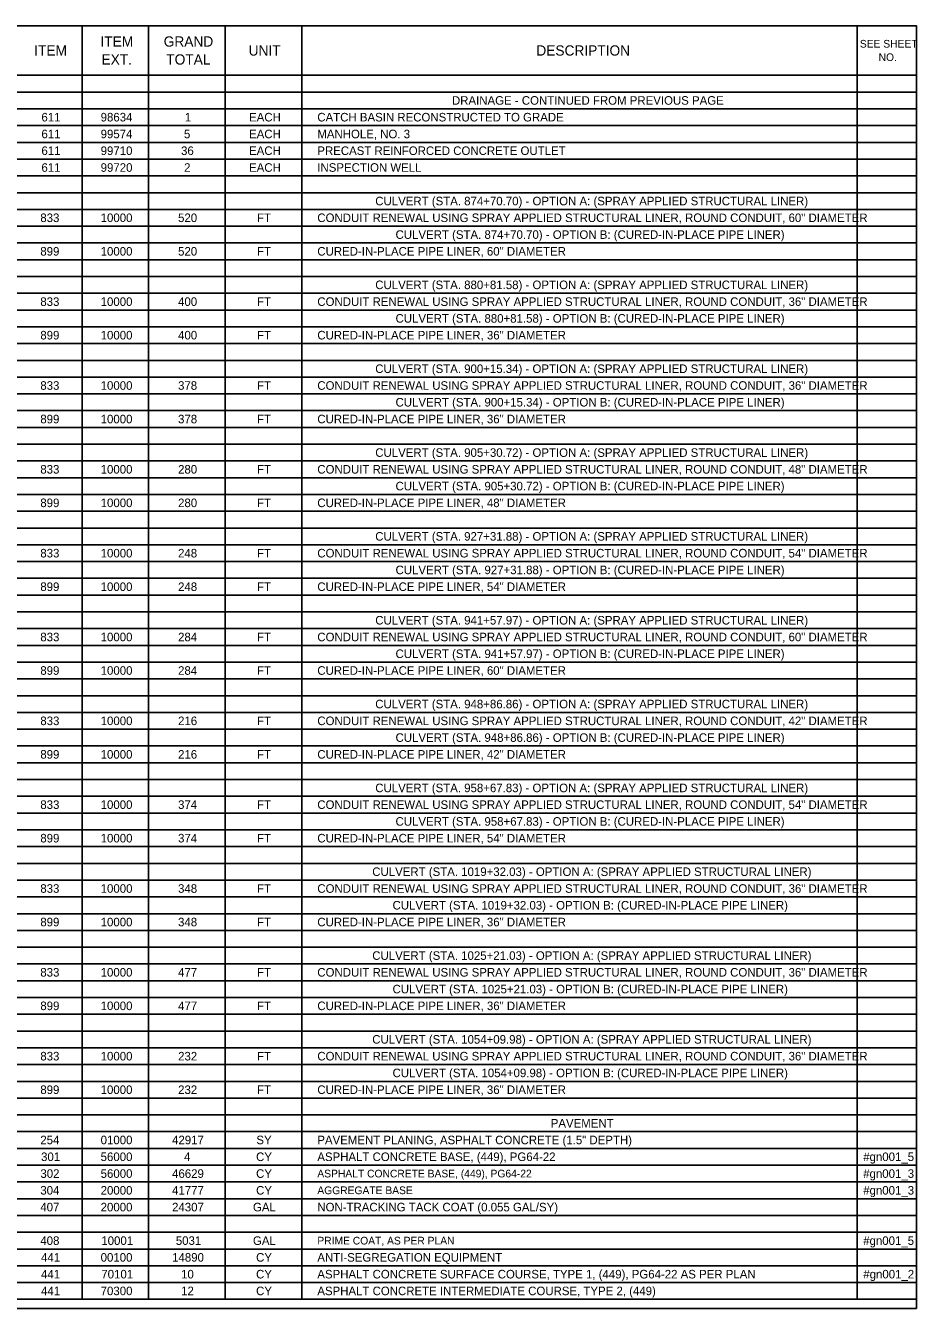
# Model space of a CAD drawing. Extents: x -542 to 295, y -281 to 32.
# Drawn here: x -400.45 to -385.84, y -70.59 to -49.59 of the extents above; entities that cross this region are included whole.
import ezdxf

# ---------------------------------------------------------------- set-up
doc = ezdxf.new("R2010")
doc.units = 0
for name, color, linetype in [('SC_Scratch1', 7, 'Continuous'), ('SH_Data', 7, 'Continuous'), ('SH_Text', 7, 'Continuous')]:
    doc.layers.add(name, color=color, linetype=linetype)

msp = doc.modelspace()

# ---------------------------------------------------------------- linework, layer by layer
at = {"layer": 'SC_Scratch1'}
msp.add_lwpolyline([(-416.359, -49.593), (-385.859, -49.593), (-385.859, -70.593), (-416.359, -70.593)], close=True, dxfattribs=at)
at = {"layer": 'SH_Data'}
for p, q in [((-416.359, -49.593), (-385.859, -49.593)), ((-399.523, -49.593), (-399.523, -70.444)), ((-398.437, -49.593), (-398.437, -70.444)), ((-397.182, -49.593), (-397.182, -70.444)), ((-395.926, -49.593), (-395.926, -70.444)), ((-386.827, -49.593), (-386.827, -70.444)), ((-385.859, -49.593), (-385.859, -70.444)), ((-416.359, -50.405), (-385.859, -50.405)), ((-416.359, -50.68), (-385.859, -50.68)), ((-416.359, -50.954), (-385.859, -50.954)), ((-416.359, -51.229), (-385.859, -51.229)), ((-416.359, -51.503), (-385.859, -51.503)), ((-416.359, -51.778), (-385.859, -51.778)), ((-416.359, -52.052), (-385.859, -52.052)), ((-416.359, -52.327), (-385.859, -52.327)), ((-416.359, -52.327), (-385.859, -52.327)), ((-416.359, -52.601), (-385.859, -52.601)), ((-416.359, -52.876), (-385.859, -52.876)), ((-416.359, -53.15), (-385.859, -53.15)), ((-416.359, -53.425), (-385.859, -53.425)), ((-416.359, -53.699), (-385.859, -53.699)), ((-416.359, -53.974), (-385.859, -53.974)), ((-416.359, -54.248), (-385.859, -54.248)), ((-416.359, -54.523), (-385.859, -54.523)), ((-416.359, -54.797), (-385.859, -54.797)), ((-416.359, -55.072), (-385.859, -55.072)), ((-416.359, -55.346), (-385.859, -55.346)), ((-416.359, -55.621), (-385.859, -55.621)), ((-416.359, -55.895), (-385.859, -55.895)), ((-416.359, -56.17), (-385.859, -56.17)), ((-416.359, -56.444), (-385.859, -56.444)), ((-416.359, -56.719), (-385.859, -56.719)), ((-416.359, -56.993), (-385.859, -56.993)), ((-416.359, -57.268), (-385.859, -57.268)), ((-416.359, -57.542), (-385.859, -57.542)), ((-416.359, -57.817), (-385.859, -57.817)), ((-416.359, -58.091), (-385.859, -58.091)), ((-416.359, -58.366), (-385.859, -58.366)), ((-416.359, -58.64), (-385.859, -58.64)), ((-416.359, -58.915), (-385.859, -58.915)), ((-416.359, -59.189), (-385.859, -59.189)), ((-416.359, -59.464), (-385.859, -59.464)), ((-416.359, -59.738), (-385.859, -59.738)), ((-416.359, -60.013), (-385.859, -60.013)), ((-416.359, -60.287), (-385.859, -60.287)), ((-416.359, -60.562), (-385.859, -60.562)), ((-416.359, -60.836), (-385.859, -60.836)), ((-416.359, -61.111), (-385.859, -61.111)), ((-416.359, -61.385), (-385.859, -61.385)), ((-416.359, -61.66), (-385.859, -61.66)), ((-416.359, -61.935), (-385.859, -61.935)), ((-416.359, -62.209), (-385.859, -62.209)), ((-416.359, -62.484), (-385.859, -62.484)), ((-416.359, -62.758), (-385.859, -62.758)), ((-416.359, -63.033), (-385.859, -63.033)), ((-416.359, -63.307), (-385.859, -63.307)), ((-416.359, -63.582), (-385.859, -63.582)), ((-416.359, -63.856), (-385.859, -63.856)), ((-416.359, -64.131), (-385.859, -64.131)), ((-416.359, -64.405), (-385.859, -64.405)), ((-416.359, -64.68), (-385.859, -64.68)), ((-416.359, -64.954), (-385.859, -64.954)), ((-416.359, -65.229), (-385.859, -65.229)), ((-416.359, -65.503), (-385.859, -65.503)), ((-416.359, -65.778), (-385.859, -65.778)), ((-416.359, -66.052), (-385.859, -66.052)), ((-416.359, -66.327), (-385.859, -66.327)), ((-416.359, -66.601), (-385.859, -66.601)), ((-416.359, -66.876), (-385.859, -66.876)), ((-416.359, -67.15), (-385.859, -67.15)), ((-416.359, -67.425), (-385.859, -67.425)), ((-416.359, -67.425), (-385.859, -67.425)), ((-416.359, -67.699), (-385.859, -67.699)), ((-416.359, -67.974), (-385.859, -67.974)), ((-416.359, -68.248), (-385.859, -68.248)), ((-416.359, -68.523), (-385.859, -68.523)), ((-416.359, -68.797), (-385.859, -68.797)), ((-416.359, -69.072), (-385.859, -69.072)), ((-416.359, -69.346), (-385.859, -69.346)), ((-416.359, -69.621), (-385.859, -69.621)), ((-416.359, -69.895), (-385.859, -69.895)), ((-416.359, -70.17), (-385.859, -70.17)), ((-416.359, -70.444), (-385.859, -70.444)), ((-416.359, -70.444), (-385.859, -70.444))]:
    msp.add_line(p, q, dxfattribs=at)

# ---------------------------------------------------------------- texts
at = {"layer": 'SH_Text'}
for s, height, p in [('ITEM', 0.168, (-399.222, -49.936)), ('GRAND ', 0.168, (-398.186, -49.936)), ('ITEM', 0.168, (-400.307, -50.083)), ('UNIT', 0.168, (-396.795, -50.083)), ('DESCRIPTION', 0.168, (-392.083, -50.083)), ('SEE SHEET ', 0.126, (-386.784, -49.952)), ('EXT.', 0.168, (-399.205, -50.23)), ('TOTAL', 0.168, (-398.144, -50.23)), ('NO.', 0.126, (-386.477, -50.172)), ('DRAINAGE - CONTINUED FROM PREVIOUS PAGE', 0.14, (-393.465, -50.887)), ('611', 0.14, (-400.189, -51.161)), ('98634', 0.14, (-399.219, -51.161)), ('1', 0.14, (-397.841, -51.161)), ('EACH', 0.14, (-396.788, -51.161)), ('CATCH BASIN RECONSTRUCTED TO GRADE', 0.14, (-395.67, -51.161)), ('611', 0.14, (-400.189, -51.436)), ('99574', 0.14, (-399.219, -51.436)), ('5', 0.14, (-397.854, -51.436)), ('EACH', 0.14, (-396.788, -51.436)), ('MANHOLE, NO. 3', 0.14, (-395.67, -51.436)), ('611', 0.14, (-400.189, -51.71)), ('99710', 0.14, (-399.219, -51.71)), ('36', 0.14, (-397.902, -51.71)), ('EACH', 0.14, (-396.788, -51.71)), ('PRECAST REINFORCED CONCRETE OUTLET', 0.14, (-395.67, -51.71)), ('611', 0.14, (-400.189, -51.985)), ('99720', 0.14, (-399.219, -51.985)), ('2', 0.14, (-397.852, -51.985)), ('EACH', 0.14, (-396.788, -51.985)), ('INSPECTION WELL', 0.14, (-395.67, -51.985)), ('CULVERT (STA. 874+70.70) - OPTION A: (SPRAY APPLIED STRUCTURAL LINER)', 0.14, (-394.721, -52.534)), ('833', 0.14, (-400.207, -52.808)), ('10000', 0.14, (-399.219, -52.808)), ('520', 0.14, (-397.951, -52.808)), ('FT', 0.14, (-396.658, -52.808)), ('CONDUIT RENEWAL USING SPRAY APPLIED STRUCTURAL LINER, ROUND CONDUIT, 60" DIAMETER', 0.14, (-395.67, -52.808)), ('CULVERT (STA. 874+70.70) - OPTION B: (CURED-IN-PLACE PIPE LINER)', 0.14, (-394.389, -53.083)), ('899', 0.14, (-400.207, -53.357)), ('10000', 0.14, (-399.219, -53.357)), ('520', 0.14, (-397.951, -53.357)), ('FT', 0.14, (-396.658, -53.357)), ('CURED-IN-PLACE PIPE LINER, 60" DIAMETER', 0.14, (-395.67, -53.357)), ('CULVERT (STA. 880+81.58) - OPTION A: (SPRAY APPLIED STRUCTURAL LINER)', 0.14, (-394.721, -53.906)), ('833', 0.14, (-400.207, -54.181)), ('10000', 0.14, (-399.219, -54.181)), ('400', 0.14, (-397.951, -54.181)), ('FT', 0.14, (-396.658, -54.181)), ('CONDUIT RENEWAL USING SPRAY APPLIED STRUCTURAL LINER, ROUND CONDUIT, 36" DIAMETER', 0.14, (-395.67, -54.181)), ('CULVERT (STA. 880+81.58) - OPTION B: (CURED-IN-PLACE PIPE LINER)', 0.14, (-394.389, -54.455)), ('899', 0.14, (-400.207, -54.73)), ('10000', 0.14, (-399.219, -54.73)), ('400', 0.14, (-397.951, -54.73)), ('FT', 0.14, (-396.658, -54.73)), ('CURED-IN-PLACE PIPE LINER, 36" DIAMETER', 0.14, (-395.67, -54.73)), ('CULVERT (STA. 900+15.34) - OPTION A: (SPRAY APPLIED STRUCTURAL LINER)', 0.14, (-394.721, -55.279)), ('833', 0.14, (-400.207, -55.554)), ('10000', 0.14, (-399.219, -55.554)), ('378', 0.14, (-397.951, -55.554)), ('FT', 0.14, (-396.658, -55.554)), ('CONDUIT RENEWAL USING SPRAY APPLIED STRUCTURAL LINER, ROUND CONDUIT, 36" DIAMETER', 0.14, (-395.67, -55.554)), ('CULVERT (STA. 900+15.34) - OPTION B: (CURED-IN-PLACE PIPE LINER)', 0.14, (-394.389, -55.828)), ('899', 0.14, (-400.207, -56.103)), ('10000', 0.14, (-399.219, -56.103)), ('378', 0.14, (-397.951, -56.103)), ('FT', 0.14, (-396.658, -56.103)), ('CURED-IN-PLACE PIPE LINER, 36" DIAMETER', 0.14, (-395.67, -56.103)), ('CULVERT (STA. 905+30.72) - OPTION A: (SPRAY APPLIED STRUCTURAL LINER)', 0.14, (-394.721, -56.652)), ('833', 0.14, (-400.207, -56.926)), ('10000', 0.14, (-399.219, -56.926)), ('280', 0.14, (-397.951, -56.926)), ('FT', 0.14, (-396.658, -56.926)), ('CONDUIT RENEWAL USING SPRAY APPLIED STRUCTURAL LINER, ROUND CONDUIT, 48" DIAMETER', 0.14, (-395.67, -56.926)), ('CULVERT (STA. 905+30.72) - OPTION B: (CURED-IN-PLACE PIPE LINER)', 0.14, (-394.389, -57.201)), ('899', 0.14, (-400.207, -57.475)), ('10000', 0.14, (-399.219, -57.475)), ('280', 0.14, (-397.951, -57.475)), ('FT', 0.14, (-396.658, -57.475)), ('CURED-IN-PLACE PIPE LINER, 48" DIAMETER', 0.14, (-395.67, -57.475)), ('CULVERT (STA. 927+31.88) - OPTION A: (SPRAY APPLIED STRUCTURAL LINER)', 0.14, (-394.721, -58.024)), ('833', 0.14, (-400.207, -58.299)), ('10000', 0.14, (-399.219, -58.299)), ('248', 0.14, (-397.951, -58.299)), ('FT', 0.14, (-396.658, -58.299)), ('CONDUIT RENEWAL USING SPRAY APPLIED STRUCTURAL LINER, ROUND CONDUIT, 54" DIAMETER', 0.14, (-395.67, -58.299)), ('CULVERT (STA. 927+31.88) - OPTION B: (CURED-IN-PLACE PIPE LINER)', 0.14, (-394.389, -58.573)), ('899', 0.14, (-400.207, -58.848)), ('10000', 0.14, (-399.219, -58.848)), ('248', 0.14, (-397.951, -58.848)), ('FT', 0.14, (-396.658, -58.848)), ('CURED-IN-PLACE PIPE LINER, 54" DIAMETER', 0.14, (-395.67, -58.848)), ('CULVERT (STA. 941+57.97) - OPTION A: (SPRAY APPLIED STRUCTURAL LINER)', 0.14, (-394.721, -59.397)), ('833', 0.14, (-400.207, -59.671)), ('10000', 0.14, (-399.219, -59.671)), ('284', 0.14, (-397.951, -59.671)), ('FT', 0.14, (-396.658, -59.671)), ('CONDUIT RENEWAL USING SPRAY APPLIED STRUCTURAL LINER, ROUND CONDUIT, 60" DIAMETER', 0.14, (-395.67, -59.671)), ('CULVERT (STA. 941+57.97) - OPTION B: (CURED-IN-PLACE PIPE LINER)', 0.14, (-394.389, -59.946)), ('899', 0.14, (-400.207, -60.22)), ('10000', 0.14, (-399.219, -60.22)), ('284', 0.14, (-397.951, -60.22)), ('FT', 0.14, (-396.658, -60.22)), ('CURED-IN-PLACE PIPE LINER, 60" DIAMETER', 0.14, (-395.67, -60.22)), ('CULVERT (STA. 948+86.86) - OPTION A: (SPRAY APPLIED STRUCTURAL LINER)', 0.14, (-394.721, -60.769)), ('833', 0.14, (-400.207, -61.044)), ('10000', 0.14, (-399.219, -61.044)), ('216', 0.14, (-397.951, -61.044)), ('FT', 0.14, (-396.658, -61.044)), ('CONDUIT RENEWAL USING SPRAY APPLIED STRUCTURAL LINER, ROUND CONDUIT, 42" DIAMETER', 0.14, (-395.67, -61.044)), ('CULVERT (STA. 948+86.86) - OPTION B: (CURED-IN-PLACE PIPE LINER)', 0.14, (-394.389, -61.318)), ('899', 0.14, (-400.207, -61.593)), ('10000', 0.14, (-399.219, -61.593)), ('216', 0.14, (-397.951, -61.593)), ('FT', 0.14, (-396.658, -61.593)), ('CURED-IN-PLACE PIPE LINER, 42" DIAMETER', 0.14, (-395.67, -61.593)), ('CULVERT (STA. 958+67.83) - OPTION A: (SPRAY APPLIED STRUCTURAL LINER)', 0.14, (-394.721, -62.142)), ('833', 0.14, (-400.207, -62.416)), ('10000', 0.14, (-399.219, -62.416)), ('374', 0.14, (-397.951, -62.416)), ('FT', 0.14, (-396.658, -62.416)), ('CONDUIT RENEWAL USING SPRAY APPLIED STRUCTURAL LINER, ROUND CONDUIT, 54" DIAMETER', 0.14, (-395.67, -62.416)), ('CULVERT (STA. 958+67.83) - OPTION B: (CURED-IN-PLACE PIPE LINER)', 0.14, (-394.389, -62.691)), ('899', 0.14, (-400.207, -62.965)), ('10000', 0.14, (-399.219, -62.965)), ('374', 0.14, (-397.951, -62.965)), ('FT', 0.14, (-396.658, -62.965)), ('CURED-IN-PLACE PIPE LINER, 54" DIAMETER', 0.14, (-395.67, -62.965)), ('CULVERT (STA. 1019+32.03) - OPTION A: (SPRAY APPLIED STRUCTURAL LINER)', 0.14, (-394.77, -63.514)), ('833', 0.14, (-400.207, -63.789)), ('10000', 0.14, (-399.219, -63.789)), ('348', 0.14, (-397.951, -63.789)), ('FT', 0.14, (-396.658, -63.789)), ('CONDUIT RENEWAL USING SPRAY APPLIED STRUCTURAL LINER, ROUND CONDUIT, 36" DIAMETER', 0.14, (-395.67, -63.789)), ('CULVERT (STA. 1019+32.03) - OPTION B: (CURED-IN-PLACE PIPE LINER)', 0.14, (-394.438, -64.063)), ('899', 0.14, (-400.207, -64.338)), ('10000', 0.14, (-399.219, -64.338)), ('348', 0.14, (-397.951, -64.338)), ('FT', 0.14, (-396.658, -64.338)), ('CURED-IN-PLACE PIPE LINER, 36" DIAMETER', 0.14, (-395.67, -64.338)), ('CULVERT (STA. 1025+21.03) - OPTION A: (SPRAY APPLIED STRUCTURAL LINER)', 0.14, (-394.77, -64.887)), ('833', 0.14, (-400.207, -65.161)), ('10000', 0.14, (-399.219, -65.161)), ('477', 0.14, (-397.951, -65.161)), ('FT', 0.14, (-396.658, -65.161)), ('CONDUIT RENEWAL USING SPRAY APPLIED STRUCTURAL LINER, ROUND CONDUIT, 36" DIAMETER', 0.14, (-395.67, -65.161)), ('CULVERT (STA. 1025+21.03) - OPTION B: (CURED-IN-PLACE PIPE LINER)', 0.14, (-394.438, -65.436)), ('899', 0.14, (-400.207, -65.71)), ('10000', 0.14, (-399.219, -65.71)), ('477', 0.14, (-397.951, -65.71)), ('FT', 0.14, (-396.658, -65.71)), ('CURED-IN-PLACE PIPE LINER, 36" DIAMETER', 0.14, (-395.67, -65.71)), ('CULVERT (STA. 1054+09.98) - OPTION A: (SPRAY APPLIED STRUCTURAL LINER)', 0.14, (-394.77, -66.259)), ('833', 0.14, (-400.207, -66.534)), ('10000', 0.14, (-399.219, -66.534)), ('232', 0.14, (-397.95, -66.534)), ('FT', 0.14, (-396.658, -66.534)), ('CONDUIT RENEWAL USING SPRAY APPLIED STRUCTURAL LINER, ROUND CONDUIT, 36" DIAMETER', 0.14, (-395.67, -66.534)), ('CULVERT (STA. 1054+09.98) - OPTION B: (CURED-IN-PLACE PIPE LINER)', 0.14, (-394.438, -66.808)), ('899', 0.14, (-400.207, -67.083)), ('10000', 0.14, (-399.219, -67.083)), ('232', 0.14, (-397.95, -67.083)), ('FT', 0.14, (-396.658, -67.083)), ('CURED-IN-PLACE PIPE LINER, 36" DIAMETER', 0.14, (-395.67, -67.083)), ('PAVEMENT', 0.14, (-391.847, -67.632)), ('254', 0.14, (-400.207, -67.906)), ('01000', 0.14, (-399.219, -67.906)), ('42917', 0.14, (-398.049, -67.906)), ('SY', 0.14, (-396.668, -67.906)), ('PAVEMENT PLANING, ASPHALT CONCRETE (1.5" DEPTH)', 0.14, (-395.67, -67.906)), ('301', 0.14, (-400.195, -68.181)), ('56000', 0.14, (-399.219, -68.181)), ('CY', 0.14, (-396.673, -68.181)), ('ASPHALT CONCRETE BASE, (449), PG64-22 ', 0.14, (-395.67, -68.181)), ('#gn001_5', 0.14, (-386.729, -68.181)), ('4', 0.14, (-397.853, -68.181)), ('302', 0.14, (-400.206, -68.456)), ('56000', 0.14, (-399.219, -68.456)), ('46629', 0.14, (-398.049, -68.456)), ('CY', 0.14, (-396.673, -68.456)), ('ASPHALT CONCRETE BASE, (449), PG64-22 ', 0.126, (-395.67, -68.449)), ('#gn001_3', 0.14, (-386.729, -68.456)), ('304', 0.14, (-400.207, -68.73)), ('20000', 0.14, (-399.219, -68.73)), ('41777', 0.14, (-398.049, -68.73)), ('CY', 0.14, (-396.673, -68.73)), ('AGGREGATE BASE', 0.126, (-395.67, -68.723)), ('#gn001_3', 0.14, (-386.729, -68.73)), ('407', 0.14, (-400.207, -69.005)), ('20000', 0.14, (-399.219, -69.005)), ('24307', 0.14, (-398.049, -69.005)), ('GAL', 0.14, (-396.724, -69.005)), ('NON-TRACKING TACK COAT (0.055 GAL/SY)', 0.14, (-395.67, -69.005)), ('408', 0.14, (-400.207, -69.554)), ('10001', 0.14, (-399.208, -69.554)), ('5031', 0.14, (-397.988, -69.554)), ('GAL', 0.14, (-396.724, -69.554)), ('PRIME COAT, AS PER PLAN', 0.126, (-395.67, -69.547)), ('#gn001_5', 0.14, (-386.729, -69.554)), ('441', 0.14, (-400.195, -69.828)), ('00100', 0.14, (-399.219, -69.828)), ('14890', 0.14, (-398.048, -69.828)), ('CY', 0.14, (-396.673, -69.828)), ('ANTI-SEGREGATION EQUIPMENT', 0.14, (-395.67, -69.828)), ('441', 0.14, (-400.195, -70.103)), ('70101', 0.14, (-399.208, -70.103)), ('10', 0.14, (-397.902, -70.103)), ('CY', 0.14, (-396.673, -70.103)), ('ASPHALT CONCRETE SURFACE COURSE, TYPE 1, (449), PG64-22 AS PER PLAN', 0.14, (-395.67, -70.103)), ('#gn001_2', 0.14, (-386.728, -70.103)), ('441', 0.14, (-400.195, -70.377)), ('70300', 0.14, (-399.219, -70.377)), ('12', 0.14, (-397.901, -70.377)), ('CY', 0.14, (-396.673, -70.377)), ('ASPHALT CONCRETE INTERMEDIATE COURSE, TYPE 2, (449)', 0.14, (-395.67, -70.377))]:
    msp.add_text(s, height=height, dxfattribs=at).set_placement(p)

doc.saveas('drawing.dxf')
